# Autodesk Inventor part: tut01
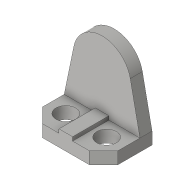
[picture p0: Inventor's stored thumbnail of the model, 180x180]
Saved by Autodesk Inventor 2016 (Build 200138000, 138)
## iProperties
Created: 2015-03
Part Number: tut01
Material: Generic
Document SubType Name: Modeling
Designer: Sandeep
Density: 1 g/cm^3
Appearance: Default
Author: Sandeep
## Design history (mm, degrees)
sketch "Sketch1"
  geometry: L1 (-100, 0)-(100, 0); L2 (100, 0)-(100, -90); L3 (100, -90)-(62, -128); L4 (62, -128)-(-62, -128); L5 (-62, -128)-(-100, -90); L6 (-100, -90)-(-100, 0); L7 (0, 83.092)-(0, -329.034); C1 r 26 at (-54, -74); C2 r 26 at (54, -74); 1 further point
  constraints: 14 end point, 3 perpendicular, 3 point on line, 2 centre point, 1 horizontal, 1 midpoint, 1 parallel, 1 vertical, 3 other
  dimensions: "d0" = 52 diameter of C2; "d1" = 90 distance of L1.end L2.end; "d2" = 124 distance of L3.end L4.end; "d3" = 74 distance from line of C2.centre L1; "d4" = 128 distance between parallel lines of L4 L1; "d5" = 46 distance from line of L2 C2.centre
extrude "Extrusion1" new body sketch "Sketch1" distance "d6" = 32; taper "d7" = 0 deg
sketch "Sketch2"
  geometry: 1 further point
sketch "Sketch3"
  geometry: 1 further point
sketch "Sketch4"
  geometry: L1 (200, -32)-(0, -32) reference; L2 (200, -32)-(174.418, -155.424); L3 (25.582, -155.424)-(0, -32); L4 (200, -32)-(0, -32); L5 (100, 0)-(100, -232.138); L6 (0, 0)-(200, 0) reference; A1 r 76 centre (100, -140) between (25.582, -155.424) and (174.418, -155.424)
  constraints: 8 end point, 2 point on circle, 2 tangent, 1 centre point, 1 collinear, 1 perpendicular, 1 point on line
  dimensions: "d8" = 76 radius of A1; "d9" = 108 distance from line of L1 A1.centre
extrude "Extrusion2" join sketch "Sketch4" distance "d10" = 32; taper "d11" = 0 deg
sketch "Sketch5"
  geometry: L1 (162, 32)-(-38, 32) reference; L2 (44, 32)-(80, 32); L3 (80, 32)-(80, 42); L4 (80, 42)-(44, 42); L5 (44, 42)-(44, 32); L6 (-38, 0)-(-38, 32) reference; 1 further point
  constraints: 8 end point, 2 parallel, 1 horizontal, 1 perpendicular, 1 point on line
  dimensions: "d12" = 10 distance of L4.end L2.start; "d13" = 82 distance between parallel lines of L6 L5; "d14" = 36 distance of L3.end L4.end
extrude "Extrusion3" join sketch "Sketch5" stored distance "d15" = 32; taper "d16" = 0 deg
body "Solid1"
